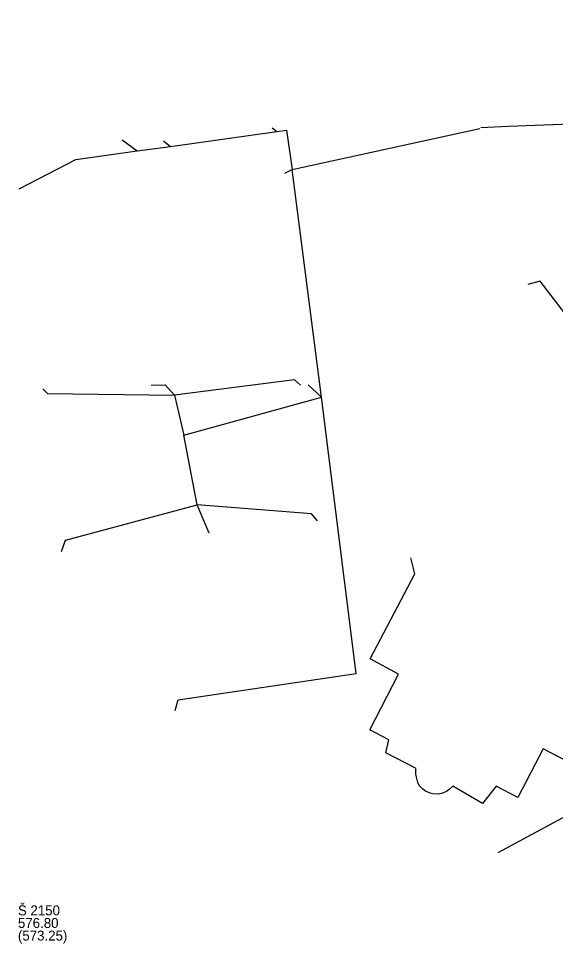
# Model space of a CAD drawing. Extents: x -643575 to -638952, y -1116425 to -1112056.
# Drawn here: x -642122.5 to -642052.1, y -1115292.1 to -1115170.9 of the extents above; entities that cross this region are included whole.
import ezdxf

# ---------------------------------------------------------------- set-up
doc = ezdxf.new("R2010")
doc.units = 0
doc.layers.add('K Označení šachty', color=7, linetype='Continuous')
doc.layers.add('K Přípojka', color=7, linetype='Continuous')

msp = doc.modelspace()

# ---------------------------------------------------------------- linework, layer by layer
at = {"layer": 'K Přípojka'}
for points in [[(-642061.92, -1115185.23), (-642058.33, -1115185.03), (-642047.89, -1115184.63), (-642040.49, -1115184.6), (-642038.47, -1115184.27), (-642036.64, -1115184.21), (-642027.35, -1115183.03), (-642016.94, -1115181.95), (-642007.74, -1115181.2), (-641998.18, -1115177.63), (-641982.95, -1115170.94)], [(-642122.46, -1115193.23), (-642115.02, -1115189.41), (-642106.98, -1115188.29), (-642102.61, -1115187.69), (-642088.68, -1115185.75), (-642087.39, -1115185.57), (-642086.65, -1115190.71)], [(-642089.31, -1115185.27), (-642088.68, -1115185.75)], [(-642086.65, -1115190.71), (-642062.08, -1115185.33)], [(-642108.94, -1115186.81), (-642106.98, -1115188.29)], [(-642103.54, -1115186.98), (-642102.61, -1115187.69)], [(-642087.64, -1115191.18), (-642086.65, -1115190.71)], [(-642082.83, -1115220.53), (-642086.65, -1115190.71)], [(-642045.96, -1115218.5), (-642046.65, -1115214.77), (-642050.85, -1115209.65), (-642054.17, -1115205.34), (-642055.78, -1115205.79)], [(-642085.56, -1115218.94), (-642086.34, -1115218.26), (-642102.07, -1115220.26)], [(-642119.35, -1115219.43), (-642118.74, -1115220.03), (-642102.07, -1115220.26)], [(-642105.13, -1115218.95), (-642103.33, -1115218.91), (-642102.07, -1115220.26)], [(-642084.58, -1115218.91), (-642082.83, -1115220.53)], [(-642102.07, -1115220.26), (-642100.88, -1115225.5)], [(-642102, -1115261.58), (-642101.6, -1115260.18), (-642078.26, -1115256.73), (-642082.83, -1115220.53)], [(-642100.88, -1115225.5), (-642082.83, -1115220.53)], [(-642099.11, -1115234.62), (-642100.88, -1115225.5)], [(-642116.92, -1115240.74), (-642116.36, -1115239.24), (-642099.11, -1115234.62)], [(-642097.55, -1115238.33), (-642099.11, -1115234.62)], [(-642083.35, -1115236.73), (-642084.15, -1115235.79), (-642099.11, -1115234.62)], [(-642050.66, -1115268.22), (-642053.75, -1115266.6), (-642057.07, -1115272.95), (-642059.92, -1115271.46), (-642061.71, -1115273.74), (-642065.63, -1115271.48), (-642066.09, -1115271.9), (-642066.46, -1115272.17), (-642067.11, -1115272.44), (-642067.55, -1115272.52), (-642068.21, -1115272.48), (-642068.6, -1115272.39), (-642069.17, -1115272.14), (-642069.52, -1115271.87), (-642070, -1115271.37), (-642070.19, -1115271.01), (-642070.38, -1115270.3), (-642070.44, -1115269.91), (-642070.44, -1115269.27), (-642070.42, -1115269.16), (-642074.4, -1115267.09), (-642074, -1115265.39), (-642076.48, -1115264.09), (-642072.72, -1115256.79), (-642076.43, -1115254.78), (-642070.59, -1115243.66), (-642071.11, -1115241.57)], [(-642059.67, -1115280.18), (-642046.78, -1115273.24), (-642033.19, -1115254.16), (-642015.52, -1115245.36)]]:
    msp.add_lwpolyline(points, dxfattribs=at)

# ---------------------------------------------------------------- texts
at = {"layer": 'K Označení šachty'}
for s, p in [('Š 2150', (-642122.61, -1115288.39)), ('576.80', (-642122.61, -1115290.04)), ('(573.25)', (-642122.61, -1115291.69))]:
    msp.add_text(s, height=1.3, dxfattribs=at).set_placement(p)

doc.saveas('drawing.dxf')
